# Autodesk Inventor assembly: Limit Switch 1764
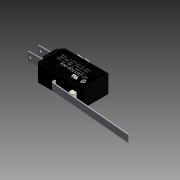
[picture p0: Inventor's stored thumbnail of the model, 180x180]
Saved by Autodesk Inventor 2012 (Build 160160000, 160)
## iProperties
Shininess: 0.0
Created: 2002-01
Part Number: Limit Switch 1764
Document SubType Name: Assembly
Density: 0.0
Volumn: 0.0
Area: 0.0
PropertySet Name: Model Information
Control State: 0
Master: False
Checked Out: False
Author: Administrator
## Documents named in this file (6)
- R:\CAD Archives\Electronics_1764\Limit_Switch_1764\Limit_Switch_1764.iam
- R:\CAD Archives\Electronics_1764\Limit_Switch_1764\COM_1764.ipt
- R:\CAD Archives\Electronics_1764\Limit_Switch_1764\Limit_Switch_Part_3_1764.ipt
- R:\CAD Archives\Electronics_1764\Limit_Switch_1764\Limit_Switch_Part_6_1764.ipt
- R:\CAD Archives\Electronics_1764\Limit_Switch_1764\Limit_Switch_Part_1_1764.ipt
- R:\CAD Archives\Electronics_1764\Limit_Switch_1764\Limit_Switch_Part_4_1764.ipt
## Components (6 placed, 5 different names)
1. Limit_Switch_Part_3_1764:1 — Mate:3, Flush:6, Flush:7, Flush:8
2. Limit_Switch_Part_6_1764:1 — Flush:5, Mate:3, Flush:6, Flush:7, Mate:5, Flush:9, Mate:6, Mate:7, Flush:11, Mate:8
3. COM_1764:1 — Flush:5
4. Limit_Switch_Part_1_1764:1 — Flush:8, Mate:5, Flush:9
5. Limit_Switch_Part_4_1764:1 — Flush:10, Mate:6, Flush:12, Mate:8
6. Limit_Switch_Part_4_1764:2 — Flush:10, Mate:7, Flush:11, Flush:12
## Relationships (13: Flush 8, Mate 5)
- Flush:5: Limit_Switch_Part_6_1764:1 ↔ COM_1764:1
- Mate:3: Limit_Switch_Part_3_1764:1 ↔ Limit_Switch_Part_6_1764:1
- Flush:6: Limit_Switch_Part_3_1764:1 ↔ Limit_Switch_Part_6_1764:1
- Flush:7: Limit_Switch_Part_3_1764:1 ↔ Limit_Switch_Part_6_1764:1
- Flush:8: Limit_Switch_Part_3_1764:1 ↔ Limit_Switch_Part_1_1764:1
- Mate:5: Limit_Switch_Part_6_1764:1 ↔ Limit_Switch_Part_1_1764:1
- Flush:9: Limit_Switch_Part_6_1764:1 ↔ Limit_Switch_Part_1_1764:1
- Flush:10: Limit_Switch_Part_4_1764:1 ↔ Limit_Switch_Part_4_1764:2
- Mate:6: Limit_Switch_Part_6_1764:1 ↔ Limit_Switch_Part_4_1764:1
- Mate:7: Limit_Switch_Part_6_1764:1 ↔ Limit_Switch_Part_4_1764:2
- Flush:11: Limit_Switch_Part_6_1764:1 ↔ Limit_Switch_Part_4_1764:2
- Flush:12: Limit_Switch_Part_4_1764:1 ↔ Limit_Switch_Part_4_1764:2
- Mate:8: Limit_Switch_Part_6_1764:1 ↔ Limit_Switch_Part_4_1764:1
